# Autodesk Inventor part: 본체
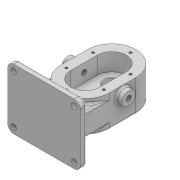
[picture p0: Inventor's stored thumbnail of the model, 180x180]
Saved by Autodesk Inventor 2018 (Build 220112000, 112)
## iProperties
Created: 2020-09
Part Number: 본체
Material: Generic
Document SubType Name: Modeling
Designer: Administrator
Density: 1 g/cm^3
Appearance: Default
Author: Administrator
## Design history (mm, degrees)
sketch "스케치2"
  geometry: L1 (0, -22)-(0, 22); L2 (40, -22)-(40, 22); L3 (-40, 22)-(-40, -22); A1 r 40 centre (0, -22) between (-40, -22) and (40, -22); A2 r 40 centre (0, 22) between (40, 22) and (-40, 22); 1 further point
  constraints: 8 end point, 4 point on circle, 4 tangent, 2 centre point, 1 midpoint, 1 parallel, 1 vertical
  dimensions: "d8" = 40 radius of A2; "d9" = 44 distance of L2.start L2.end
extrude "돌출1" new body sketch "스케치2" distance "d11" = 53; taper "d12" = 0 deg
sketch "스케치3"
  geometry: C1 r 19 at (0, 22); A1 r 40 centre (0, 22) between (40, 22) and (-40, 22) reference; 1 further point
  constraints: 1 centre point, 1 coincident
  dimensions: "d13" = 38 diameter of C1
extrude "돌출2" join sketch "스케치3" distance "d14" = 17; taper "d15" = 0 deg
node "작업 평면1"
sketch "스케치4"
  geometry: L1 (40, 53)-(-40, 53) reference; L2 (-60, 83)-(-60, -17); L3 (60, 83)-(60, -17); L4 (-19, -17)-(19, -17) reference; L5 (0, -17)-(0, 83); L6 (60, -17)-(-60, -17); L7 (60, 83)-(-60, 83); 1 further point
  constraints: 10 end point, 2 parallel, 1 horizontal, 1 midpoint, 1 perpendicular, 1 vertical
  dimensions: "d19" = 100 distance of L5.start L5.end; "d89" = 120 distance of L3.end L2.end; "d90" = 30 distance between parallel lines of L1 L7; "d91" = 70 distance between parallel lines of L1 L6; "d92" = 60 distance between parallel lines of L3 L5
extrude "돌출3" join sketch "스케치4" distance "d20" = 10; taper "d21" = 0 deg
sketch "스케치5"
  geometry: L1 (60, 17)-(-60, 17) reference; L2 (0, -8)-(0, -45); L3 (40, -45)-(40, -8); L4 (-40, -45)-(-40, -8); L5 (-40, -45)-(40, -45); L6 (-40, -8)-(40, -8); 1 further point
  constraints: 10 end point, 2 horizontal, 1 vertical
  dimensions: "d23" = 37 distance of L2.start L2.end; "d26" = 40 distance between parallel lines of L2 L3; "d27" = 40 distance between parallel lines of L2 L4; "d93" = 25 distance between parallel lines of L1 L6; "d94" = 62 distance between parallel lines of L1 L5; "d95" = 20 distance from line of L1.start L3; "d96" = 25 distance from line of L2.start L1
extrude "돌출4" join sketch "스케치5" stored distance "d28" = 10; taper "d29" = 0 deg
sketch "스케치6"
  geometry: L1 (22, 53)-(-22, 53) reference; L2 (0, 53)-(0, 39); C1 r 11 at (0, 39); 1 further point
  constraints: 2 end point, 1 centre point, 1 coincident, 1 midpoint, 1 vertical
  dimensions: "d30" = 14 distance of L2.start L2.end; "d31" = 22 diameter of C1
extrude "돌출5" join sketch "스케치6" stored distance "d32" = 100; taper "d33" = 0 deg
sketch "스케치7"
  geometry: L1 (-24, 22)-(-24, -22); L2 (24, 22)-(24, -22); A1 r 40 centre (0, 22) between (40, 22) and (-40, 22) reference; A2 r 24 centre (0, 22) between (24, 22) and (-24, 22); A3 r 40 centre (0, -22) between (-40, -22) and (40, -22) reference; A4 r 24 centre (0, -22) between (-24, -22) and (24, -22); 1 further point
  constraints: 4 end point, 4 point on circle, 2 centre point, 2 coincident, 2 tangent, 2 vertical
  dimensions: "d34" = 48 diameter of A2; "d35" = 48 diameter of A4
extrude "돌출6" cut sketch "스케치7" distance "d36" = 29; taper "d37" = 0 deg
sketch "스케치8"
  geometry: C1 r 12.5 at (0, 22); C2 r 12.5 at (0, -22); A1 r 24 centre (0, 22) between (24, 22) and (-24, 22) reference; A2 r 24 centre (0, -22) between (-24, -22) and (24, -22) reference; 1 further point
  constraints: 2 centre point, 2 coincident
  dimensions: "d38" = 25 diameter of C1; "d39" = 25 diameter of C2
extrude "돌출7" cut sketch "스케치8" distance "d40" = 15; taper "d41" = 0 deg
sketch "스케치9"
  geometry: C1 r 12.5 at (0, 0) reference; C2 r 8.5 at (0, 0); 1 further point
  constraints: 1 centre point, 1 coincident
  dimensions: "d42" = 17 diameter of C2
extrude "돌출8" cut sketch "스케치9" extent not by distance; stored distance "d43" = 15; taper "d44" = 0 deg
sketch "스케치10"
  geometry: C1 r 19 at (0, 0) reference; C2 r 14 at (0, 0); 1 further point
  constraints: 1 centre point, 1 coincident
  dimensions: "d45" = 28 diameter of C2
extrude "돌출9" cut sketch "스케치10" distance "d46" = 7.3; taper "d47" = 0 deg
fillet "모깎기1" dims "d48" = 0.5
chamfer "모따기1" distance "d49" = 0.7; stored, may be unused: second distance "d50" = 2, angle "d51" = 30 deg
sketch "스케치11"
  geometry: C1 r 12.5 at (0, 22) reference; 8 further points
  dimensions: "d97" = 31 distance of C1.centre point (31, 22); "d98" = 38.01316 distance of point (0, 0) point (31, 22); "d99" = 53.82379 distance of C1.centre point (31, -22); "d100" = 38.01316 distance of point (0, 0) point (31, -22); "d101" = 31 distance of C1.centre point (0, 53); "d102" = 53 distance of point (0, 0) point (0, 53); "d103" = 75 distance of C1.centre point (0, -53); "d104" = 31 distance of C1.centre point (-31, 22); "d105" = 53.82379 distance of C1.centre point (-31, -22); "d106" = 53 distance of point (0, 0) point (0, -53); "d107" = 38.01316 distance of point (0, 0) point (-31, 22); "d108" = 38.01316 distance of point (0, 0) point (-31, -22)
hole "구멍1" sketch "스케치11" at (-31, 22), (31, 22), (0, 53), (0, -53), (31, -22), (-31, -22) diameter "d54" = 4.134; stored, may be unused: countersink angle "d58" = 90 deg, drill point angle "d60" = 118 deg; dims "d55" = 10, "d56" = 4, "d57" = 2, "d59" = 12
sketch "스케치12"
  geometry: C1 r 11 at (0, 0) reference; 2 further points
  constraints: 1 coincident
hole "구멍2" sketch "스케치12" at (0, 0) diameter "d61" = 8.376; stored, may be unused: countersink angle "d65" = 90 deg, drill point angle "d67" = 118 deg; dims "d62" = 20, "d63" = 4, "d64" = 2, "d66" = 27.3
fillet "모깎기2" dims "d68" = 10
fillet "모깎기3" dims "d69" = 3
sketch "스케치13"
  geometry: C1 r 4.5 at (-50, 7); C2 r 4.5 at (-50, -73); C3 r 4.5 at (50, -73); C4 r 4.5 at (50, 7); A1 r 10 centre (-50, 7) between (-50, 17) and (-60, 7) reference; A2 r 10 centre (-50, -73) between (-60, -73) and (-50, -83) reference; A3 r 10 centre (50, -73) between (50, -83) and (60, -73) reference; A4 r 10 centre (50, 7) between (60, 7) and (50, 17) reference; 1 further point
  constraints: 4 centre point, 4 coincident
  dimensions: "d70" = 9 diameter of C1; "d71" = 9 diameter of C2; "d72" = 9 diameter of C3; "d73" = 9 diameter of C4
extrude "돌출10" cut sketch "스케치13" extent not by distance; stored distance "d74" = 7.3; taper "d75" = 0 deg
chamfer "모따기2" distance "d76" = 1; stored, may be unused: second distance "d77" = 2, angle "d78" = 45 deg
chamfer "모따기3" distance "d79" = 1; stored, may be unused: second distance "d80" = 2, angle "d81" = 45 deg
fillet "모깎기4" dims "d82" = 3
sketch "스케치14"
  geometry: L1 (-50, -83)-(50, -83) reference; L2 (-60, 7)-(-60, -73) reference; 2 further points
  constraints: 1 other
  dimensions: "d84" = 12 distance from line of L1 point (0, -71); "d85" = 60 distance from line of L2 point (0, -71)
feature "엠보싱1" sketch "스케치14" dims "d86" = 0.5, "d87" = 0
node "솔리드1"
